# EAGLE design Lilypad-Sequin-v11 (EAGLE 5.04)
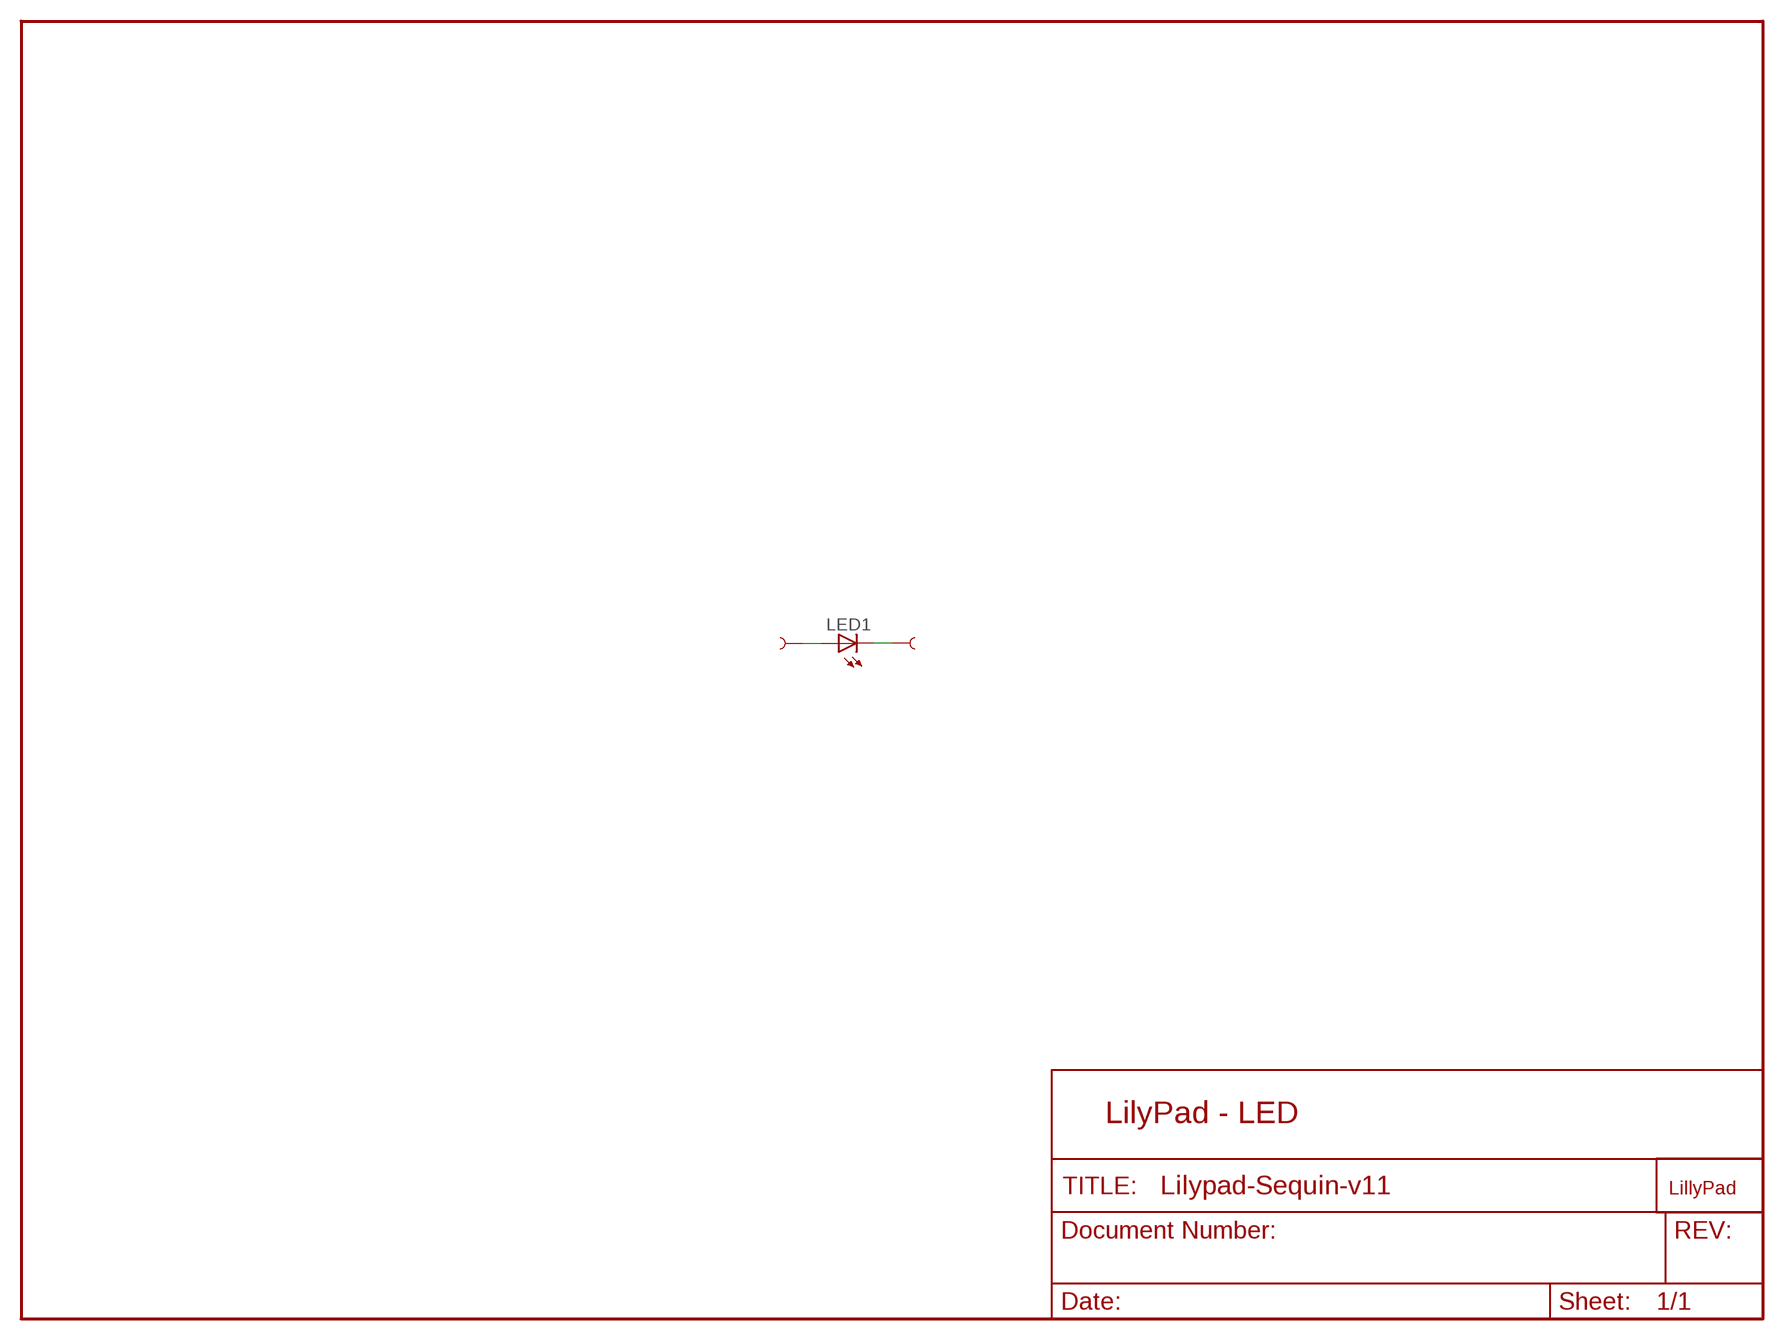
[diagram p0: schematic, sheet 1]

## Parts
LED1  LED1206  [LED-1206]
U$1  SEWTAP11  [PETAL-TINY]
U$2  SEWTAP11  [PETAL-TINY]
U$3  LOGO-LPL-TINY  [LOGO-L-TINY]

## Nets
A: LED1.A U$1.1
K: LED1.C U$2.1

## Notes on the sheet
- LilyPad - LED

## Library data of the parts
LED1 = LilyPad-Wearables:LED: LEDs
U$1 U$2 = LilyPad-Wearables:SEWTAP
U$3 = LilyPad-Wearables:LOGO-LP

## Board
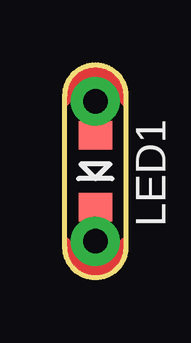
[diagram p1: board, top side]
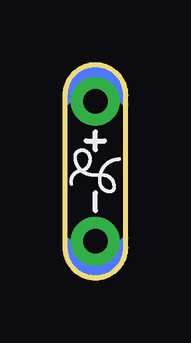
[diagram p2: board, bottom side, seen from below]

Size 2.54 x 8.89 mm. Coordinates in mm from the lower left corner, seen from the top.
Outline: 0,7.62 arc-90 1.27,8.89 arc-90 2.54,7.62 2.54,1.27 arc-90 1.27,0 arc-90 0,1.27 0,7.62
Copper layers (1*16): Top 0.035mm / dielectric 1.5mm / Bottom 0.035mm
Design rules "SparkFun": minimum track width 8mil, minimum drill 20mil, track to track 8mil, track to pad 8mil, pad to pad 8mil, via to via 8mil, smd to smd 8mil, copper to edge 8mil, drill to drill 8mil, minimum pad ring 12mil, minimum via ring 10mil, stop-mask expansion 4mil, vias tented up to drill 20mil, thermal gap 10mil

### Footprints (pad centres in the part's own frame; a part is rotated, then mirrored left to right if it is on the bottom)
LED-1206 = smd 1.2 x 1.4: A -1.5,0; C 1.5,0
PETAL-TINY = drill 1.016 pad 2.032 round: 1 0,0

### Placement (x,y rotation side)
LED1  1.27,4.45 270 top
U$1  1.27,7.37 0 top
U$2  1.27,1.52 180 top
U$3  1.27,4.45 270 bottom

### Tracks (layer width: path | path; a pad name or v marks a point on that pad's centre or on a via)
A
  Top 0.203: LED1.A U$1.1
K
  Top 0.203: LED1.C U$2.1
